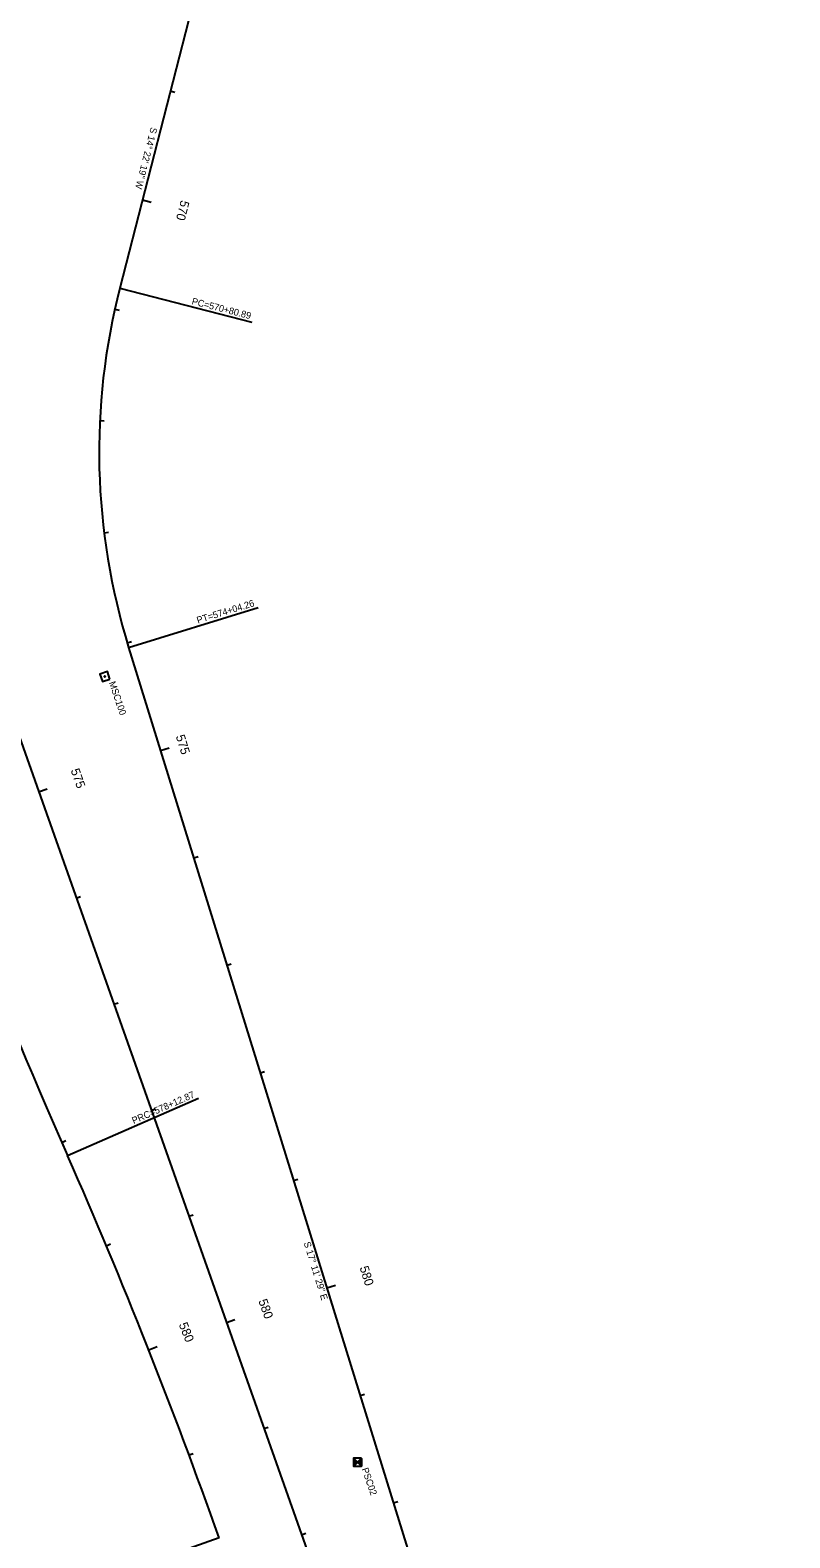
# Model space of a CAD drawing. Extents: x 2004390 to 2008791, y 1133870 to 1140084.
# Drawn here: x 2006401 to 2007075, y 1135092 to 1136432 of the extents above; entities that cross this region are included whole.
import ezdxf

# ---------------------------------------------------------------- set-up
doc = ezdxf.new("R2010")
doc.units = 0
for name, color, linetype in [('RD_HC_Cl', 7, 'Continuous'), ('RD_HC_Data', 7, 'Continuous'), ('RD_HC_Data_Tic', 7, 'Continuous'), ('RD_HC_Survey', 7, 'Continuous'), ('RD_HC_Survey_txCode', 7, 'Continuous'), ('RD_HC_TX_Sta50', 7, 'Continuous')]:
    doc.layers.add(name, color=color, linetype=linetype)

msp = doc.modelspace()

# ---------------------------------------------------------------- linework, layer by layer
at = {"layer": 'RD_HC_Cl'}
for p, q in [((2005036.1, 1139633.5), (2007075.2, 1133869.8)), ((2006616.6, 1136735.3), (2006480.1, 1136202.9)), ((2006488, 1135883.7), (2006962.2, 1134351.1))]:
    msp.add_line(p, q, dxfattribs=at)
for centre, radius, start, end in [((2007048.8, 1136057.2), 587, 165.6281, 197.1914), ((2012591.2, 1138138.7), 6726, 199.48201, 203.72857), ((2001920.6, 1133448.3), 4930, 19.482, 23.7286)]:
    msp.add_arc(centre, radius, start, end, dxfattribs=at)
at = {"layer": 'RD_HC_Data'}
for p, q in [((2006480.1, 1136202.9), (2006597.5, 1136172.8)), ((2006488, 1135883.7), (2006603, 1135919.3)), ((2006433.8, 1135432.1), (2006549.9, 1135483.1)), ((2006568.4, 1135092.5), (2006454.9, 1135052.3))]:
    msp.add_line(p, q, dxfattribs=at)
at = {"layer": 'RD_HC_Data_Tic'}
for p, q in [((2006525, 1136378.1), (2006528.9, 1136377.1)), ((2006500.2, 1136281.3), (2006508, 1136279.3)), ((2006475.7, 1136184.3), (2006479.6, 1136183.5)), ((2006462.4, 1136085.3), (2006466.4, 1136085.1)), ((2006466.2, 1135985.5), (2006470.1, 1135986)), ((2006486.8, 1135887.8), (2006490.6, 1135888.9)), ((2006516.3, 1135792.2), (2006523.9, 1135794.6)), ((2006408.1, 1135755.3), (2006415.7, 1135757.9)), ((2006545.9, 1135696.7), (2006549.7, 1135697.9)), ((2006441.5, 1135661), (2006445.3, 1135662.3)), ((2006575.4, 1135601.2), (2006579.2, 1135602.4)), ((2006474.8, 1135566.7), (2006478.6, 1135568)), ((2006605, 1135505.6), (2006608.8, 1135506.8)), ((2006508.2, 1135472.4), (2006512, 1135473.8)), ((2006428.7, 1135443.9), (2006432.3, 1135445.5)), ((2006634.5, 1135410.1), (2006638.3, 1135411.3)), ((2006541.5, 1135378.2), (2006545.3, 1135379.5)), ((2006468.2, 1135352.1), (2006471.9, 1135353.6)), ((2006664.1, 1135314.6), (2006671.7, 1135316.9)), ((2006574.9, 1135283.9), (2006582.4, 1135286.6)), ((2006505.9, 1135259.4), (2006513.3, 1135262.4)), ((2006693.6, 1135219), (2006697.5, 1135220.2)), ((2006608.2, 1135189.6), (2006612, 1135190.9)), ((2006541.7, 1135166.1), (2006545.4, 1135167.4)), ((2006723.2, 1135123.5), (2006727, 1135124.7)), ((2006641.6, 1135095.3), (2006645.4, 1135096.7))]:
    msp.add_line(p, q, dxfattribs=at)
at = {"layer": 'RD_HC_Survey'}
for p, q in [((2006687.8, 1135163.2), (2006694.8, 1135156.1)), ((2006694.8, 1135163.2), (2006687.8, 1135156.1)), ((2006687.8, 1135163.1), (2006687.8, 1135156.2)), ((2006687.9, 1135163.1), (2006687.9, 1135156.2)), ((2006687.9, 1135163), (2006687.9, 1135156.3)), ((2006688, 1135163), (2006688, 1135156.3)), ((2006688, 1135162.9), (2006688, 1135156.4)), ((2006688.1, 1135162.9), (2006688.1, 1135156.4)), ((2006688.1, 1135162.8), (2006688.1, 1135156.5)), ((2006688.2, 1135162.8), (2006688.2, 1135156.5)), ((2006688.2, 1135162.7), (2006688.2, 1135156.6)), ((2006688.3, 1135162.7), (2006688.3, 1135156.6)), ((2006688.3, 1135162.6), (2006688.3, 1135156.7)), ((2006688.4, 1135162.6), (2006688.4, 1135156.7)), ((2006688.4, 1135162.5), (2006688.4, 1135156.8)), ((2006688.5, 1135162.5), (2006688.5, 1135156.8)), ((2006688.5, 1135162.4), (2006688.5, 1135156.9)), ((2006688.6, 1135162.4), (2006688.6, 1135156.9)), ((2006688.6, 1135162.3), (2006688.6, 1135157)), ((2006688.7, 1135162.3), (2006688.7, 1135157)), ((2006688.7, 1135162.2), (2006688.7, 1135157.1)), ((2006688.8, 1135162.2), (2006688.8, 1135157.1)), ((2006688.8, 1135162.1), (2006688.8, 1135157.2)), ((2006688.9, 1135162.1), (2006688.9, 1135157.2)), ((2006688.9, 1135162), (2006688.9, 1135157.3)), ((2006689, 1135162), (2006689, 1135157.3)), ((2006689, 1135161.9), (2006689, 1135157.4)), ((2006689.1, 1135161.9), (2006689.1, 1135157.4)), ((2006689.1, 1135161.8), (2006689.1, 1135157.5)), ((2006689.2, 1135161.8), (2006689.2, 1135157.5)), ((2006689.2, 1135161.7), (2006689.2, 1135157.6)), ((2006689.3, 1135161.7), (2006689.3, 1135157.6)), ((2006689.3, 1135161.6), (2006689.3, 1135157.7)), ((2006689.4, 1135161.6), (2006689.4, 1135157.7)), ((2006689.4, 1135161.5), (2006689.4, 1135157.8)), ((2006689.5, 1135161.5), (2006689.5, 1135157.8)), ((2006689.5, 1135161.4), (2006689.5, 1135157.9)), ((2006689.6, 1135161.4), (2006689.6, 1135157.9)), ((2006689.6, 1135161.3), (2006689.6, 1135158)), ((2006689.7, 1135161.3), (2006689.7, 1135158)), ((2006689.7, 1135161.2), (2006689.7, 1135158.1)), ((2006689.8, 1135161.2), (2006689.8, 1135158.1)), ((2006689.8, 1135161.1), (2006689.8, 1135158.2)), ((2006689.9, 1135161.1), (2006689.9, 1135158.2)), ((2006689.9, 1135161), (2006689.9, 1135158.3)), ((2006690, 1135161), (2006690, 1135158.3)), ((2006690, 1135160.9), (2006690, 1135158.4)), ((2006690.1, 1135160.9), (2006690.1, 1135158.4)), ((2006690.1, 1135160.8), (2006690.1, 1135158.5)), ((2006690.2, 1135160.8), (2006690.2, 1135158.5)), ((2006690.2, 1135160.7), (2006690.2, 1135158.6)), ((2006690.3, 1135160.7), (2006690.3, 1135158.6)), ((2006690.3, 1135160.6), (2006690.3, 1135158.7)), ((2006690.4, 1135160.6), (2006690.4, 1135158.7)), ((2006690.4, 1135160.5), (2006690.4, 1135158.8)), ((2006690.5, 1135160.5), (2006690.5, 1135158.8)), ((2006690.5, 1135160.4), (2006690.5, 1135158.9)), ((2006690.6, 1135160.4), (2006690.6, 1135158.9)), ((2006690.6, 1135160.3), (2006690.6, 1135159)), ((2006690.7, 1135160.3), (2006690.7, 1135159)), ((2006690.7, 1135160.2), (2006690.7, 1135159.1)), ((2006690.8, 1135160.2), (2006690.8, 1135159.1)), ((2006690.8, 1135160.1), (2006690.8, 1135159.2)), ((2006690.9, 1135160.1), (2006690.9, 1135159.2)), ((2006690.9, 1135160), (2006690.9, 1135159.3)), ((2006691, 1135160), (2006691, 1135159.3)), ((2006691, 1135159.9), (2006691, 1135159.4)), ((2006691.1, 1135159.9), (2006691.1, 1135159.4)), ((2006691.1, 1135159.8), (2006691.1, 1135159.5)), ((2006691.2, 1135159.8), (2006691.2, 1135159.5)), ((2006691.2, 1135159.7), (2006691.2, 1135159.6)), ((2006691.3, 1135159.7), (2006691.3, 1135159.6)), ((2006691.3, 1135159.7), (2006691.3, 1135159.6)), ((2006691.4, 1135159.8), (2006691.4, 1135159.5)), ((2006691.4, 1135159.7), (2006691.4, 1135159.6)), ((2006691.5, 1135159.9), (2006691.5, 1135159.4)), ((2006691.5, 1135159.8), (2006691.5, 1135159.5)), ((2006691.6, 1135160), (2006691.6, 1135159.3)), ((2006691.6, 1135159.9), (2006691.6, 1135159.4)), ((2006691.7, 1135160.1), (2006691.7, 1135159.2)), ((2006691.7, 1135160), (2006691.7, 1135159.3)), ((2006691.8, 1135160.2), (2006691.8, 1135159.1)), ((2006691.8, 1135160.1), (2006691.8, 1135159.2)), ((2006691.9, 1135160.3), (2006691.9, 1135159)), ((2006691.9, 1135160.2), (2006691.9, 1135159.1)), ((2006692, 1135160.4), (2006692, 1135158.9)), ((2006692, 1135160.3), (2006692, 1135159)), ((2006692.1, 1135160.5), (2006692.1, 1135158.8)), ((2006692.1, 1135160.4), (2006692.1, 1135158.9)), ((2006692.2, 1135160.6), (2006692.2, 1135158.7)), ((2006692.2, 1135160.5), (2006692.2, 1135158.8)), ((2006692.3, 1135160.7), (2006692.3, 1135158.6)), ((2006692.3, 1135160.6), (2006692.3, 1135158.7)), ((2006692.4, 1135160.8), (2006692.4, 1135158.5)), ((2006692.4, 1135160.7), (2006692.4, 1135158.6)), ((2006692.5, 1135160.9), (2006692.5, 1135158.4)), ((2006692.5, 1135160.8), (2006692.5, 1135158.5)), ((2006692.6, 1135161), (2006692.6, 1135158.3)), ((2006692.6, 1135160.9), (2006692.6, 1135158.4)), ((2006692.7, 1135161.1), (2006692.7, 1135158.2)), ((2006692.7, 1135161), (2006692.7, 1135158.3)), ((2006692.8, 1135161.2), (2006692.8, 1135158.1)), ((2006692.8, 1135161.1), (2006692.8, 1135158.2)), ((2006692.9, 1135161.3), (2006692.9, 1135158)), ((2006692.9, 1135161.2), (2006692.9, 1135158.1)), ((2006693, 1135161.4), (2006693, 1135157.9)), ((2006693, 1135161.3), (2006693, 1135158)), ((2006693.1, 1135161.5), (2006693.1, 1135157.8)), ((2006693.1, 1135161.4), (2006693.1, 1135157.9)), ((2006693.2, 1135161.6), (2006693.2, 1135157.7)), ((2006693.2, 1135161.5), (2006693.2, 1135157.8)), ((2006693.3, 1135161.7), (2006693.3, 1135157.6)), ((2006693.3, 1135161.6), (2006693.3, 1135157.7)), ((2006693.4, 1135161.8), (2006693.4, 1135157.5)), ((2006693.4, 1135161.7), (2006693.4, 1135157.6)), ((2006693.5, 1135161.9), (2006693.5, 1135157.4)), ((2006693.5, 1135161.8), (2006693.5, 1135157.5)), ((2006693.6, 1135162), (2006693.6, 1135157.3)), ((2006693.6, 1135161.9), (2006693.6, 1135157.4)), ((2006693.7, 1135162.1), (2006693.7, 1135157.2)), ((2006693.7, 1135162), (2006693.7, 1135157.3)), ((2006693.8, 1135162.2), (2006693.8, 1135157.1)), ((2006693.8, 1135162.1), (2006693.8, 1135157.2)), ((2006693.9, 1135162.3), (2006693.9, 1135157)), ((2006693.9, 1135162.2), (2006693.9, 1135157.1)), ((2006694, 1135162.4), (2006694, 1135156.9)), ((2006694, 1135162.3), (2006694, 1135157)), ((2006694.1, 1135162.5), (2006694.1, 1135156.8)), ((2006694.1, 1135162.4), (2006694.1, 1135156.9)), ((2006694.2, 1135162.6), (2006694.2, 1135156.7)), ((2006694.2, 1135162.5), (2006694.2, 1135156.8)), ((2006694.3, 1135162.7), (2006694.3, 1135156.6)), ((2006694.3, 1135162.6), (2006694.3, 1135156.7)), ((2006694.4, 1135162.8), (2006694.4, 1135156.5)), ((2006694.4, 1135162.7), (2006694.4, 1135156.6)), ((2006694.5, 1135162.9), (2006694.5, 1135156.4)), ((2006694.5, 1135162.8), (2006694.5, 1135156.5)), ((2006694.6, 1135163), (2006694.6, 1135156.3)), ((2006694.6, 1135162.9), (2006694.6, 1135156.4)), ((2006694.7, 1135163.1), (2006694.7, 1135156.2)), ((2006694.7, 1135163), (2006694.7, 1135156.3)), ((2006694.8, 1135163.1), (2006694.8, 1135156.2))]:
    msp.add_line(p, q, dxfattribs=at)
for points in [[(2006471.4, 1135855.6), (2006469.1, 1135862.3), (2006462.4, 1135860), (2006464.8, 1135853.3)], [(2006694.8, 1135163.2), (2006687.8, 1135163.2), (2006687.8, 1135156.1), (2006694.8, 1135156.1)]]:
    msp.add_lwpolyline(points, close=True, dxfattribs=at)
msp.add_circle((2006466.9, 1135857.8), 0.5, dxfattribs=at)

# ---------------------------------------------------------------- texts
at = {"layer": 'RD_HC_Data'}
for s, rotation, p in [('S 14%%d 22\' 19" W', 255.6281, (2006507.7, 1136346.3)), ('PC=570+80.89', 345.6281, (2006543.6, 1136188.7)), ('PT=574+04.26', 17.1914, (2006549.5, 1135904.8)), ('PRC=578+12.87', 23.7286, (2006492.5, 1135460.1)), ('S 17%%d 11\' 29" E', 287.1914, (2006643.4, 1135354.6))]:
    msp.add_text(s, height=6, rotation=rotation, dxfattribs=at).set_placement(p)
at = {"layer": 'RD_HC_Survey_txCode'}
for s, p in [('MSC100', (2006470.4, 1135852.4)), ('PSC02', (2006694.9, 1135153.7))]:
    msp.add_text(s, height=6, rotation=288.8025, dxfattribs=at).set_placement(p)
at = {"layer": 'RD_HC_TX_Sta50'}
for s, rotation, p in [('570', 255.6281, (2006534.4, 1136281.5)), ('575', 287.1914, (2006529.8, 1135804.8)), ('575', 289.482, (2006436.4, 1135774.5)), ('580', 287.1914, (2006693, 1135332.7)), ('580', 289.482, (2006603.1, 1135303.1)), ('580', 291.5538, (2006532.4, 1135282.1))]:
    msp.add_text(s, height=8, rotation=rotation, dxfattribs=at).set_placement(p)

doc.saveas('drawing.dxf')
